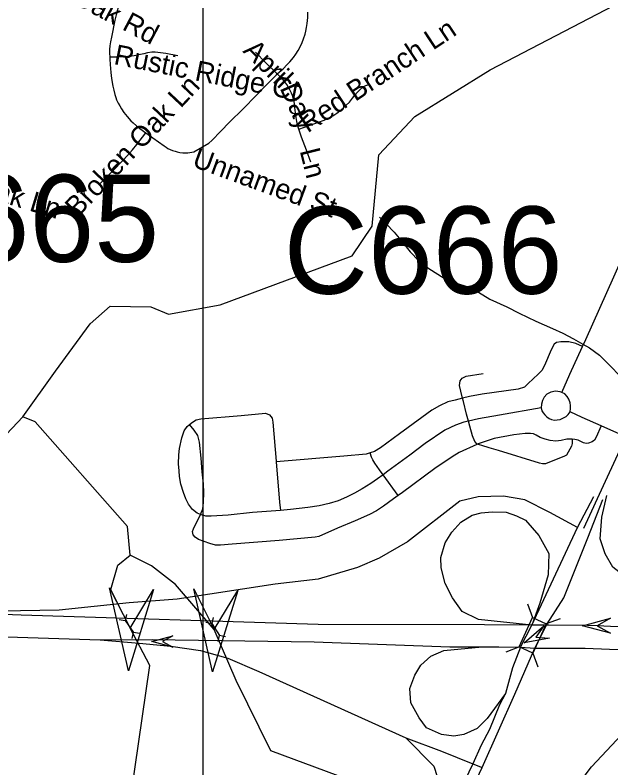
# Model space of a CAD drawing. Extents: x 1383679 to 1536984, y 460658 to 651027.
# Drawn here: x 1445312 to 1448113, y 483158 to 486697 of the extents above; entities that cross this region are included whole.
import ezdxf

# ---------------------------------------------------------------- set-up
doc = ezdxf.new("R2010")
doc.units = 0
for name, color, linetype in [('Exist Hydrographic Creek Single Shore', 7, 'Continuous'), ('Exist Hydrographic Misc Water Feature', 7, 'Continuous'), ('Exist Road Non-System Type 51', 7, 'Continuous'), ('Exist Road Non-System Type 51 Label', 7, 'Continuous'), ('Exist Road Primary Interstate Divided Center Attributed', 7, 'Continuous'), ('Exist Road Primary Interstate Ramp 1 Lane Attributed', 7, 'Continuous'), ('Exist Road Primary Interstate Structure Ovrhead Sign Attributed CELL', 7, 'Continuous'), ('Exist Road Primary US Divided Attributed', 7, 'Continuous'), ('Exist Road Primary US Structure Standard Bridge CELL', 7, 'Continuous'), ('Exist Road Secondary Structure Culvert Attributed CELL', 7, 'Continuous'), ('Exist Road Secondary Structure Culvert CELL', 7, 'Continuous'), ('Exist Road Secondary Structure Culvert Number Label', 7, 'Continuous'), ('Exist Road Secondary Structure Standard Bridge Attributed CELL', 7, 'Continuous'), ('Map Preparation Inset Cut Line', 7, 'Continuous')]:
    doc.layers.add(name, color=color, linetype=linetype)

msp = doc.modelspace()

# ---------------------------------------------------------------- linework, layer by layer
at = {"layer": 'Exist Hydrographic Creek Single Shore'}
for points in [[(1445349.2, 484808.9), (1445503.2, 485022.5), (1445665.2, 485245.7), (1445759.2, 485329.2), (1445950.2, 485325.3), (1446033.2, 485290.8), (1446276.2, 485335.2), (1446897.2, 485565.6), (1446991.2, 485704.8), (1447022.2, 486039), (1447192.2, 486219.4), (1447546.2, 486438.7), (1448127.2, 486742.2), (1448381.2, 486920.9), (1448658.2, 487049.9), (1449161.2, 487217), (1449261.2, 487215)], [(1443240.1, 483006.7), (1443460.1, 483159.8), (1443644.2, 483198.7), (1443729.2, 483305.4), (1443933.2, 483765.2), (1444025.6, 483907.6), (1444073.5, 484005.4), (1444127.2, 484108.1), (1444364.2, 484310.1), (1444508.2, 484399.2), (1444658.2, 484422.4), (1444749.2, 484394.3), (1444941.2, 484410.1), (1445017.2, 484457.9), (1445349.2, 484808.9)], [(1445854.2, 484158.7), (1445840.2, 484293.5), (1445407.2, 484784.8), (1445349.2, 484808.9)], [(1445858.2, 483032.8), (1445945.8, 483639.1), (1445852.9, 483815), (1445762, 483997.4), (1445795, 484110.6), (1445854.2, 484158.7)], [(1450631, 483341.9), (1450302.2, 483494.8), (1449922.4, 483518.4), (1449139, 483483.5), (1448970, 483355.2), (1448382.2, 482913), (1447997.1, 482655.5), (1447799, 482673.6), (1447552.4, 482785.6), (1447330.1, 482896.2), (1447225.8, 482956.7), (1446831, 483120.2), (1446515, 483238.6), (1446352.4, 483568.7), (1446248.7, 483809.2), (1446066, 484021), (1445953.2, 484107.5), (1445854.2, 484158.7)]]:
    msp.add_lwpolyline(points, dxfattribs=at)
at = {"layer": 'Exist Hydrographic Misc Water Feature'}
msp.add_lwpolyline([(1447025.3, 485747.4), (1447056.8, 485714.8), (1447094.1, 485675.5), (1447133.2, 485628.7), (1447170.4, 485584.5), (1447209.6, 485541.9), (1447257, 485504.8), (1447330.2, 485459.8), (1447385.8, 485436.6), (1447441.5, 485419), (1447491.1, 485394.2), (1447544.5, 485361.2), (1447623.8, 485325.9), (1447681.3, 485295.2), (1447760.7, 485257.5), (1447838.1, 485223.9), (1447887.7, 485200.8), (1447937.2, 485174.3), (1447980.7, 485149.7), (1448012.5, 485132.6), (1448060, 485098), (1448113, 485045.3), (1448152.2, 485004.3)], dxfattribs=at)
at = {"layer": 'Exist Road Non-System Type 51'}
for p, q in [((1448182.9, 484714.7), (1448067, 484765.7)), ((1448182.9, 484714.7), (1448086.2, 484504.1)), ((1447113.9, 484439.1), (1447042.9, 484536.4)), ((1448086.2, 484504.1), (1447985.2, 484284.2))]:
    msp.add_line(p, q, dxfattribs=at)
for points in [[(1445797.5, 486734.4), (1445793.6, 486720.9), (1445787.5, 486697.2), (1445781.7, 486672), (1445765.3, 486593.5), (1445761.3, 486570.9), (1445758.6, 486551.7), (1445756.9, 486535), (1445756.4, 486518.3), (1445757.1, 486498.9)], [(1446545.1, 486419.7), (1446571.9, 486443.5), (1446591.2, 486463.6), (1446603.4, 486477.3), (1446620.8, 486497.6), (1446631.8, 486512.8), (1446642.7, 486530.8), (1446653.8, 486549.9), (1446662.5, 486568.5), (1446669, 486585.4), (1446675.7, 486606.5), (1446679.4, 486621), (1446683, 486638.3), (1446685.5, 486657), (1446688.6, 486685.4), (1446689.1, 486710.6)], [(1446077.2, 486505.8), (1446020.8, 486516.4), (1445984.2, 486521.2), (1445970.2, 486521.9), (1445955.7, 486521.7), (1445935.6, 486519), (1445918.2, 486515.2), (1445871.8, 486504.3), (1445851.2, 486501.3), (1445818, 486499.7), (1445789.5, 486499.3), (1445757.1, 486498.9)], [(1446545.1, 486419.7), (1446543.9, 486420.9), (1446490.4, 486472.8), (1446442.1, 486521.8)], [(1445757.1, 486498.9), (1445757.4, 486490.1), (1445759.3, 486464.4), (1445762.7, 486427.1), (1445766.4, 486398.8), (1445772.5, 486363.2), (1445776.7, 486343.1), (1445781.5, 486323.5), (1445785.5, 486309.9), (1445789.7, 486298.8), (1445797.4, 486282.8), (1445805, 486269.3), (1445813.2, 486255.5), (1445824.2, 486239.4), (1445839.9, 486219.3), (1445857.1, 486200.3), (1445867.9, 486190.2), (1445883.8, 486176.4), (1445899.2, 486164.3), (1445927.4, 486143.6)], [(1445927.4, 486143.6), (1445959.7, 486120), (1446013.3, 486081.6), (1446022.1, 486075.5), (1446030.8, 486070.2), (1446041.4, 486064.8), (1446052.1, 486060.6), (1446064.3, 486056.7), (1446073.6, 486054.5), (1446087, 486051.4), (1446100.6, 486049.6), (1446116.5, 486048.7), (1446124.5, 486048.9), (1446134, 486050.1), (1446143.7, 486052.2), (1446152.1, 486054.5), (1446222.6, 486095.3), (1446236.6, 486107.9), (1446279.4, 486151.4), (1446319.9, 486193.9), (1446384.1, 486256.7), (1446445.8, 486318.4), (1446489.1, 486363.6), (1446540.8, 486415.8), (1446545.1, 486419.7)], [(1446646.8, 486160.6), (1446643.8, 486169.5), (1446637.6, 486196.2), (1446633.9, 486215.5), (1446630.6, 486236.7), (1446627.6, 486262.5), (1446623.9, 486291.9), (1446620.3, 486308), (1446616.4, 486319.2), (1446612, 486330), (1446604.2, 486345.3), (1446597.9, 486356.7), (1446589.2, 486370.8), (1446580.1, 486383.1), (1446572.4, 486392.6), (1446560.3, 486404.9), (1446545.1, 486419.7)], [(1446646.8, 486160.6), (1446673.1, 486169.3), (1446739.5, 486193.2), (1446764.6, 486203.1), (1446784.4, 486211.4), (1446805.4, 486222.7), (1446824.9, 486235.2), (1446839.4, 486245.8), (1446857, 486260.5), (1446869.4, 486272.7), (1446883.7, 486288), (1446898.5, 486306), (1446909.8, 486320.4), (1446921.4, 486334.1), (1446932.9, 486345.7), (1446947.9, 486357.4), (1446962, 486365.1), (1446970.1, 486368.2)], [(1446702.4, 486005.4), (1446681.9, 486061.1), (1446659.4, 486123.3), (1446646.8, 486160.6)], [(1445712.6, 485904.5), (1445767.2, 485959.8), (1445823, 486017.2), (1445864.6, 486063.4), (1445884.6, 486087.7), (1445927.4, 486143.6)], [(1447980.2, 485138.2), (1447995.5, 485172.1), (1448264.2, 485774.2)], [(1447980.2, 485138.2), (1447948.6, 485152.7), (1447915.9, 485160.5), (1447877.9, 485160.5), (1447858.2, 485157.9), (1447846.4, 485150), (1447832.1, 485122.6), (1447800.6, 485049.2), (1447788.9, 485025.7), (1447771.9, 485008.7), (1447724.6, 484965.4), (1447706.4, 484947.1), (1447677.6, 484937.9), (1447507.4, 484914.4), (1447448.4, 484903.9), (1447416.1, 484895.8)], [(1447881.9, 484922.8), (1447920.5, 485008.6), (1447980.2, 485138.2)], [(1447416.1, 484895.8), (1447407.8, 484928.8), (1447401.4, 484955.2), (1447403.9, 484977.2), (1447413.4, 484990.3), (1447433.5, 484999.8), (1447513.1, 485012.2)], [(1447881.9, 484922.8), (1447875.2, 484926.2), (1447853, 484928.8), (1447830.8, 484924.8), (1447812.4, 484914.4), (1447799.6, 484900.9), (1447791.1, 484885.1), (1447787.2, 484867.2), (1447786.2, 484850.2)], [(1447921.1, 484831.9), (1447922.8, 484847.9), (1447922.8, 484860.8), (1447921.1, 484873.8), (1447915.1, 484890.7), (1447906.9, 484904.3), (1447896.1, 484915.7), (1447881.9, 484922.8)], [(1447416.1, 484895.8), (1447380.4, 484886.9), (1447346.4, 484879), (1447307.1, 484860.7), (1447271.8, 484839.8), (1447224.6, 484804.4), (1447119.9, 484728.5), (1447030.9, 484663), (1447002, 484644.7), (1446982.2, 484638.8)], [(1447443.2, 484788.3), (1447434.8, 484820.8), (1447419.6, 484879.8), (1447416.1, 484895.8)], [(1447786.2, 484850.2), (1447589.9, 484816.2), (1447490.4, 484799.2), (1447443.2, 484788.3)], [(1447786.2, 484850.2), (1447789, 484837.2), (1447794.5, 484827.4), (1447803.1, 484817.2), (1447812.5, 484807.8), (1447822.8, 484800.9), (1447834.2, 484796.2), (1447847.9, 484793.2), (1447859.9, 484793.6), (1447874, 484796.2), (1447886.9, 484801.3), (1447902.2, 484810.3), (1447912.9, 484819.2), (1447921.1, 484831.9)], [(1446131.6, 484771.5), (1446145.9, 484783.5), (1446164.1, 484793.9), (1446185.1, 484799.2), (1446374.9, 484814.9), (1446488.9, 484825.3), (1446508.5, 484817.5), (1446520.2, 484801.8), (1446524.1, 484783.5), (1446539.9, 484600.2), (1446540.1, 484596.2)], [(1448067, 484765.7), (1447978.6, 484804.4), (1447921.1, 484831.9)], [(1446184.8, 484350), (1446168.1, 484355.3), (1446145.9, 484372.4), (1446127.5, 484398.6), (1446114.4, 484423.4), (1446103.9, 484452.2), (1446092.1, 484491.5), (1446085.6, 484528.2), (1446083, 484554.3), (1446080.4, 484587.1), (1446081.6, 484629), (1446085.6, 484659.1), (1446096.1, 484710.2), (1446107.9, 484742.9), (1446120.9, 484762.5), (1446131.6, 484771.5)], [(1446184.8, 484350), (1446194.4, 484375.2), (1446198.2, 484405.8), (1446200.1, 484452.5), (1446198.2, 484493.5), (1446192.5, 484549.8), (1446187.8, 484614.8), (1446180.1, 484689.2), (1446171.5, 484719.8), (1446154.4, 484745.5), (1446131.6, 484771.5)], [(1447443.2, 484788.3), (1447422.2, 484783.5), (1447383, 484769.1), (1447333.2, 484745.5), (1447240.4, 484682.7), (1447168.2, 484627.7), (1447064.9, 484553.1), (1447042.9, 484536.4)], [(1447485.2, 484679.2), (1447474.2, 484692.1), (1447463, 484719.1), (1447450.4, 484764.9), (1447443.2, 484788.3)], [(1448067, 484765.7), (1448044.1, 484713.3), (1448035.9, 484698.9), (1448025.2, 484690.6), (1448007.9, 484684.6), (1447997.2, 484683.1), (1447984.4, 484686.8), (1447958.8, 484698.2), (1447944.4, 484702), (1447930.6, 484703)], [(1447930.6, 484703), (1447923.9, 484703.5), (1447905.8, 484702.8), (1447879.2, 484696.7), (1447853.6, 484694.4), (1447827.9, 484697.4), (1447803.6, 484703.5), (1447780.1, 484711.8), (1447762.1, 484722.4), (1447749.9, 484727.7), (1447734.9, 484729.9), (1447710.6, 484729.9), (1447657.6, 484723.9), (1447564.6, 484705.8), (1447485.2, 484679.2)], [(1447930.6, 484703), (1447930.6, 484683.3), (1447927.6, 484670.2), (1447904.4, 484628.7), (1447894.9, 484623.7), (1447805.8, 484587.9), (1447791.9, 484586.7), (1447777.5, 484589.8), (1447584.8, 484649.4), (1447541.4, 484662.6), (1447506.9, 484673.2), (1447485.2, 484679.2)], [(1447485.2, 484679.2), (1447482.9, 484678.5), (1447400.5, 484640.7), (1447366.4, 484621), (1447284.8, 484565.8), (1447133.5, 484453.1), (1447113.9, 484439.1)], [(1446982.2, 484638.8), (1446962.8, 484632.9), (1446858, 484623.8), (1446540.1, 484596.2)], [(1447042.9, 484536.4), (1447026, 484559.8), (1447003.8, 484591), (1446993.4, 484605.6), (1446988.5, 484618.2), (1446982.2, 484638.8)], [(1446540.1, 484596.2), (1446555.9, 484407.8), (1446560.1, 484368.8)], [(1447042.9, 484536.4), (1447016.4, 484516.4), (1446985, 484495.4), (1446944.4, 484469.2), (1446907.8, 484449.6), (1446871.1, 484431.3), (1446830.5, 484414.2), (1446788.6, 484401.2), (1446741.5, 484389.4), (1446687.9, 484381.6), (1446606.8, 484373), (1446560.1, 484368.8)], [(1447113.9, 484439.1), (1447091.1, 484422.8), (1447044.2, 484388.1), (1447011.6, 484366.9), (1446979.1, 484349.5), (1446911.1, 484320), (1446828.6, 484284.4), (1446740.9, 484245.8), (1446722.8, 484242.8), (1446553.4, 484227.7), (1446332.4, 484209.6), (1446278, 484205), (1446254.5, 484205.8), (1446228.1, 484212.6), (1446174.4, 484231.5), (1446158.4, 484242.8), (1446150.1, 484254.2), (1446147.1, 484268.6), (1446151.6, 484281.4), (1446184.8, 484350)], [(1447741.5, 483829.8), (1447956, 484288.5), (1448032.3, 484433.7)], [(1447813.4, 483835.4), (1447891.8, 483957.7), (1448005.4, 484239.7), (1448075.6, 484419.2)], [(1446560.1, 484368.8), (1446428.6, 484358), (1446313.4, 484346.2), (1446234.9, 484341), (1446208.6, 484342.2), (1446184.8, 484350)], [(1447688.5, 483725.4), (1447741.5, 483829.8)], [(1447756, 483720.4), (1447813.4, 483835.4)]]:
    msp.add_lwpolyline(points, dxfattribs=at)
at = {"layer": 'Exist Road Primary Interstate Divided Center Attributed'}
for points in [[(1444025.6, 483907.6), (1444314.4, 483842.9), (1444529.5, 483809.6), (1444789.1, 483789.7), (1445713.1, 483760.4)], [(1447741.5, 483829.8), (1447518.4, 483831), (1446736.4, 483832.4), (1445340.9, 483876), (1444972.8, 483890.2)], [(1447822.2, 483829.1), (1447741.5, 483829.8)], [(1449281.9, 483785.1), (1449176.5, 483785.1), (1448942.1, 483792.9), (1448110.7, 483822.9), (1448047.9, 483826.5), (1448003.7, 483827.7), (1447822.2, 483829.1)], [(1445713.1, 483760.4), (1445956.5, 483762.3), (1446719.1, 483750.4), (1447356.2, 483727.9), (1447508.3, 483726.5)], [(1447508.3, 483726.5), (1447586.1, 483727.9), (1447688.5, 483725.4)], [(1447688.5, 483725.4), (1447756, 483720.4)], [(1447756, 483720.4), (1447992.2, 483720.5), (1448106.4, 483716.3), (1448903.2, 483692.9), (1449402.8, 483684.6)]]:
    msp.add_lwpolyline(points, dxfattribs=at)
at = {"layer": 'Exist Road Primary Interstate Ramp 1 Lane Attributed'}
for points in [[(1447956, 484288.5), (1447826.2, 484359.4), (1447708.2, 484418.4), (1447607.9, 484436.1), (1447489.4, 484432.2), (1447403, 484411.8), (1447156.7, 484220.3), (1447024.5, 484143.4), (1446922.4, 484099.6), (1446736.9, 484045.2), (1446534.6, 484022.4), (1446075, 483952), (1445848.6, 483933.9), (1445520.1, 483899.7), (1444972.8, 483890.2)], [(1449281.9, 483785.1), (1449082.7, 483812.5), (1448903, 483824.2), (1448750.6, 483843.7), (1448621.7, 483875), (1448485, 483918), (1448336.5, 483980.6), (1448207.6, 484035.3), (1448121.7, 484101.8), (1448086.5, 484164.3), (1448063.1, 484234.7), (1448070.9, 484336.4), (1448094.3, 484438)], [(1447316, 484099), (1447314.2, 484146.5), (1447334.2, 484216.1), (1447366.1, 484266.4), (1447408.5, 484313), (1447461.5, 484345.4), (1447502.7, 484356.8), (1447555.8, 484362.5), (1447620.6, 484360.6), (1447669.7, 484343.5), (1447711.9, 484322.1)], [(1447711.9, 484322.1), (1447773.7, 484250.1), (1447820.9, 484165.5), (1447818.4, 484065.5), (1447778.4, 483932.9), (1447741.5, 483829.8)], [(1447741.5, 483829.8), (1447491.1, 483855.4), (1447413.7, 483892.9), (1447368.1, 483956.8), (1447334.2, 484024.5), (1447316, 484099)], [(1445713.1, 483760.4), (1445895, 483743.9), (1446044.2, 483730.6), (1446183.5, 483710.7), (1446312.8, 483674.2), (1446458.8, 483611.1), (1447148.5, 483299.1)], [(1447617.7, 483507.5), (1447531.7, 483390.2), (1447484.9, 483343.3), (1447422.4, 483315.9), (1447375.5, 483308.1), (1447316.9, 483315.9), (1447246.5, 483347.2), (1447211.4, 483394.1), (1447172.3, 483464.5), (1447168.4, 483531), (1447191.9, 483593.5), (1447219.2, 483640.4), (1447266.1, 483683.4), (1447328.6, 483710.8), (1447508.3, 483726.5)], [(1446701.2, 481343.7), (1446835.6, 481622.9), (1446935.1, 481820.1), (1446996.8, 481925.6), (1447086.3, 482039.1), (1447163.6, 482153.4), (1447207.4, 482207.2), (1447292.4, 482307.9), (1447442.2, 482474.1), (1447560, 482602.5), (1447726.4, 482788.6), (1447883.7, 482979.3), (1448021.3, 483162.5), (1448141.1, 483289.7), (1448254.8, 483407.8), (1448347.2, 483473.6), (1448548.3, 483580.7), (1448828.8, 483661.9), (1449093.1, 483678.1), (1449402.8, 483684.6)], [(1447148.5, 483299.1), (1447317.7, 483236.1), (1447464.3, 483177.6)], [(1447148.5, 483299.1), (1447281.2, 483166.4), (1447311, 483073.4), (1447317.7, 482963.9), (1447281.2, 482841.1), (1447211.5, 482645.3)], [(1447464.3, 483177.6), (1447508.4, 483159.7)]]:
    msp.add_lwpolyline(points, dxfattribs=at)
at = {"layer": 'Exist Road Primary Interstate Structure Ovrhead Sign Attributed CELL'}
for points in [[(1448111.8, 483791), (1447979.3, 483826.5), (1448111.8, 483862), (1448047.9, 483826.5)], [(1446054, 483726), (1445954.6, 483752.6), (1446054, 483779.2), (1446006, 483752.6)]]:
    msp.add_lwpolyline(points, close=True, dxfattribs=at)
at = {"layer": 'Exist Road Primary US Divided Attributed'}
for points in [[(1447508.4, 483159.7), (1447661, 483505.3), (1447756, 483720.4)], [(1447688.5, 483725.4), (1447651, 483627.9), (1447617.7, 483507.5)], [(1447617.7, 483507.5), (1447589.5, 483453.9), (1447542, 483338.8), (1447503.4, 483264.4), (1447464.3, 483177.6)], [(1447464.3, 483177.6), (1447330.1, 482896.2), (1447211.5, 482645.3)], [(1446701.2, 481343.7), (1446810.6, 481613.5), (1446853.5, 481719.1), (1446916, 481855.9), (1446970.3, 481955.7), (1447039.8, 482127.7), (1447076.6, 482201.4), (1447150.3, 482361), (1447240.3, 482578), (1447482.5, 483107.5), (1447508.4, 483159.7)]]:
    msp.add_lwpolyline(points, dxfattribs=at)
at = {"layer": 'Exist Road Primary US Structure Standard Bridge CELL'}
for p, q in [((1447721.2, 483929.1), (1447745.3, 483864.5)), ((1447874.2, 483859.2), (1447809.5, 483835.1)), ((1447683.6, 483726.5), (1447618.9, 483702.5)), ((1447746.3, 483697.8), (1447770.4, 483633.2))]:
    msp.add_line(p, q, dxfattribs=at)
msp.add_lwpolyline([(1447809.5, 483835.1), (1447746.6, 483697.7), (1447682.4, 483727.1), (1447745.3, 483864.5)], close=True, dxfattribs=at)
at = {"layer": 'Exist Road Secondary Structure Culvert Attributed CELL'}
for points in [[(1445963.6, 483997.2), (1445845.1, 483615.2), (1445756.7, 484005.3), (1445852.9, 483815)], [(1446359.5, 483991.4), (1446240.9, 483609.3), (1446152.6, 483999.5), (1446248.7, 483809.2)]]:
    msp.add_lwpolyline(points, close=True, dxfattribs=at)
at = {"layer": 'Exist Road Secondary Structure Culvert CELL'}
for p, q in [((1445802.3, 483855.7), (1445830.5, 483851.2)), ((1445836.6, 483879.1), (1445830.5, 483851.2)), ((1445830.5, 483851.2), (1445868.8, 483795)), ((1446244.2, 483865), (1446237.3, 483837.3)), ((1446209.2, 483842.8), (1446237.3, 483837.3)), ((1446237.3, 483837.3), (1446273.8, 483779.9)), ((1445862.7, 483767), (1445868.8, 483795)), ((1445897, 483790.4), (1445868.8, 483795)), ((1446266.8, 483752.2), (1446273.8, 483779.9)), ((1446301.8, 483774.5), (1446273.8, 483779.9))]:
    msp.add_line(p, q, dxfattribs=at)
at = {"layer": 'Exist Road Secondary Structure Standard Bridge Attributed CELL'}
msp.add_lwpolyline([(1447824.7, 483768.7), (1447704.9, 483746.2), (1447797.4, 483825.6), (1447759.8, 483772.6)], close=True, dxfattribs=at)
at = {"layer": 'Map Preparation Inset Cut Line'}
for points in [[(1446195.4, 477316), (1383679.3, 477316), (1383679.3, 520758.2), (1458567.8, 520758.2), (1458567.8, 493672.2), (1446195.4, 493672.2), (1446195.4, 477316)], [(1446195.4, 477316), (1480703, 477316), (1498974.3, 494868.2), (1521133.6, 516155.5), (1521133.6, 520758.2), (1458567.8, 520758.2), (1458567.8, 493672.2), (1446195.4, 493672.2), (1446195.4, 477316)]]:
    msp.add_lwpolyline(points, dxfattribs=at)

# ---------------------------------------------------------------- texts
at = {"layer": 'Exist Road Non-System Type 51 Label'}
for s, rotation, p in [('Bent Oak Rd', 332.0096, (1445312.1, 486896.4)), ('Red Branch Ln', 33.4537, (1446687.7, 486140.1)), ('Rustic Ridge Ct', 348.7437, (1445772.6, 486466.6)), ('April', 315.0004, (1446379.9, 486525.1)), ('Broken Oak Ln', 46.7359, (1445606.9, 485741.9)), ('Day', 293.9626, (1446555.2, 486354.1)), ('Spreading Oak Ln', 342.9765, (1444530.7, 486037.2)), ('Unnamed St', 339.8986, (1446140, 485986.7)), ('Ln', 284.036, (1446650, 486059.1))]:
    msp.add_text(s, height=95, rotation=rotation, dxfattribs=at).set_placement(p)
at = {"layer": 'Exist Road Secondary Structure Culvert Number Label'}
for s, p in [('C665', (1444678.6, 485536.6)), ('C666', (1446575.2, 485387))]:
    msp.add_text(s, height=410.1, dxfattribs=at).set_placement(p)

doc.saveas('drawing.dxf')
